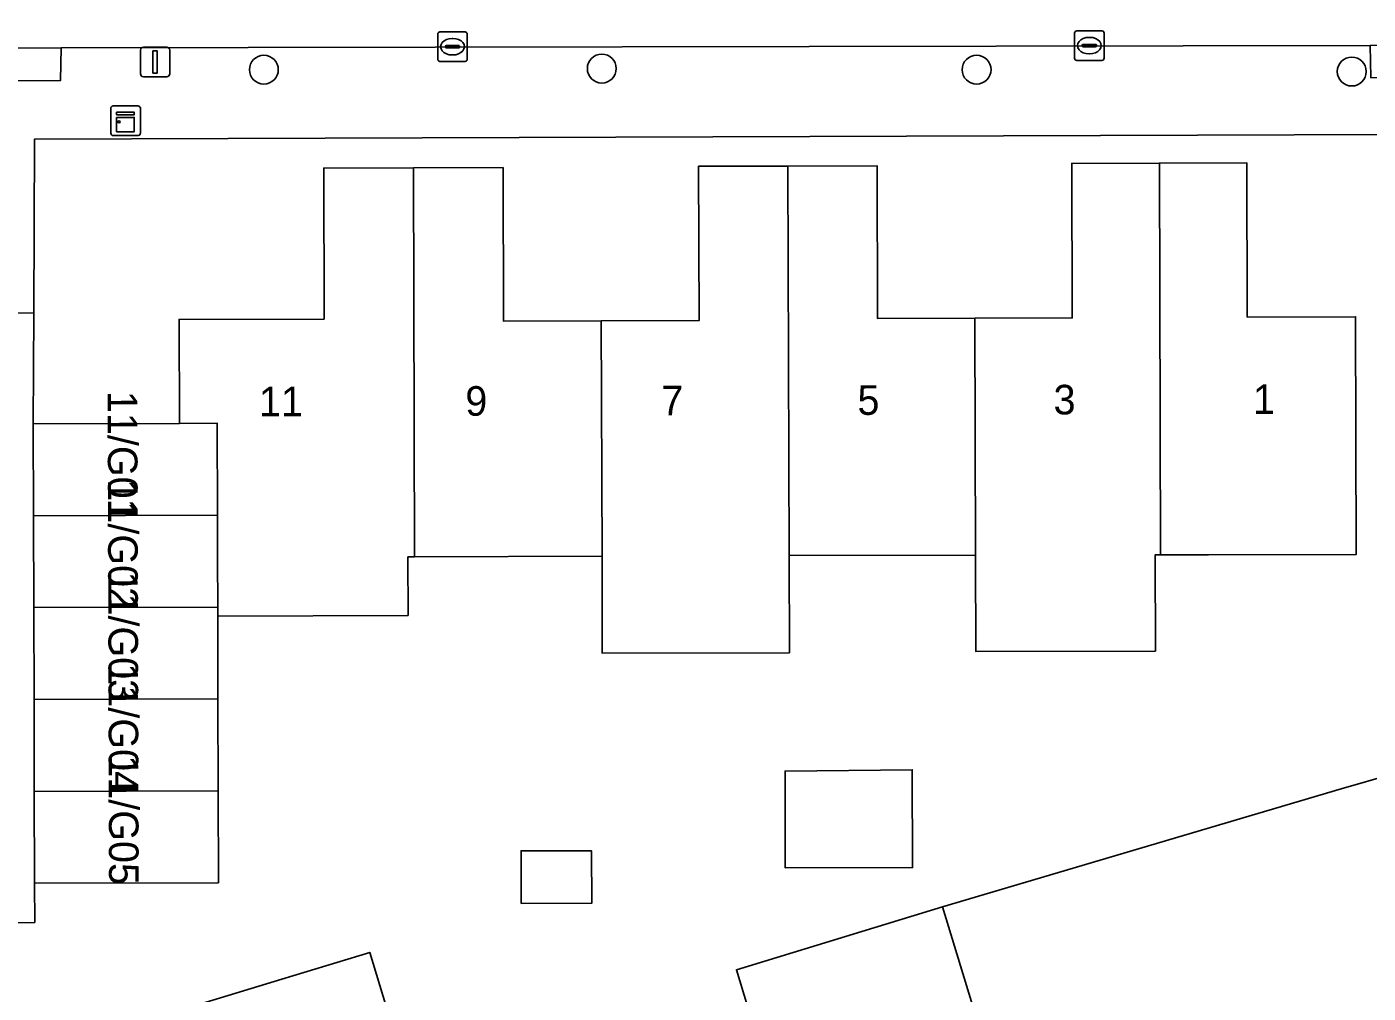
# Model space of a CAD drawing. Extents: x 160732 to 162107, y 387428 to 388479.
# Drawn here: x 161074.34 to 161119.69, y 388198.11 to 388230.78 of the extents above; entities that cross this region are included whole.
import ezdxf

# ---------------------------------------------------------------- set-up
doc = ezdxf.new("R2010")
doc.units = 0
for name, color, linetype in [('IMGEO_Boom', 7, 'Continuous'), ('IMGEO_Erf', 7, 'Continuous'), ('IMGEO_Kast', 7, 'Continuous'), ('IMGEO_Kolk', 7, 'Continuous'), ('IMGEO_Lichtmast', 7, 'Continuous'), ('IMGEO_Pand', 7, 'Continuous'), ('IMGEO_Pand_nummerreeks', 7, 'Continuous'), ('IMGEO_Parkeervlak_open', 7, 'Continuous'), ('IMGEO_Rijbaan_lokaal_open', 7, 'Continuous'), ('IMGEO_Voetpad_open', 7, 'Continuous')]:
    doc.layers.add(name, color=color, linetype=linetype)

msp = doc.modelspace()

# ---------------------------------------------------------------- linework, layer by layer
at = {"layer": 'IMGEO_Boom'}
for centre in [(161082.352, 388229.334), (161093.779, 388229.371), (161106.451, 388229.334), (161119.136, 388229.271)]:
    msp.add_circle(centre, 0.489, dxfattribs=at)
at = {"layer": 'IMGEO_Erf'}
for points in [[(161120.471, 388227.138), (161074.599, 388226.989), (161074.571, 388221.102), (161074.554, 388217.361), (161079.499, 388217.376), (161079.488, 388220.889), (161084.39, 388220.902), (161084.376, 388226.004), (161087.408, 388226.013), (161090.439, 388226.022), (161090.454, 388220.832), (161093.762, 388220.842), (161097.068, 388220.852), (161097.053, 388226.066), (161100.07, 388226.075), (161103.087, 388226.084), (161103.102, 388220.919), (161106.392, 388220.928), (161109.686, 388220.938), (161109.671, 388226.164), (161112.63, 388226.173), (161115.589, 388226.181), (161115.604, 388220.969), (161119.266, 388220.98), (161119.289, 388212.942), (161114.29, 388212.928), (161112.664, 388212.927), (161112.486, 388212.927), (161112.496, 388209.678), (161106.426, 388209.66), (161106.416, 388212.914), (161100.114, 388212.902), (161100.124, 388209.621), (161093.796, 388209.602), (161093.786, 388212.889), (161087.441, 388212.861), (161087.224, 388212.86), (161087.231, 388210.884), (161080.792, 388210.859), (161080.799, 388208.057), (161080.808, 388204.949), (161080.817, 388201.841), (161074.599, 388201.824), (161074.603, 388200.5), (161071.182, 388200.474)], [(161099.34, 388195.583), (161098.329, 388198.904), (161105.3, 388201.027), (161118.777, 388205.02), (161120.504, 388205.518)], [(161078.176, 388197.129), (161082.961, 388198.582), (161085.935, 388199.485), (161087.292, 388195.016)]]:
    msp.add_lwpolyline(points, dxfattribs=at)
for points in [[(161099.983, 388202.342), (161099.973, 388205.618), (161104.277, 388205.664), (161104.287, 388202.355)], [(161091.057, 388201.142), (161091.051, 388202.927), (161093.434, 388202.92), (161093.439, 388201.15)]]:
    msp.add_lwpolyline(points, close=True, dxfattribs=at)
at = {"layer": 'IMGEO_Kast'}
for p, q in [((161077.177, 388227.182), (161077.177, 388228.023)), ((161077.177, 388228.023), (161077.177, 388227.182)), ((161077.252, 388228.107), (161078.093, 388228.107)), ((161078.093, 388228.107), (161077.252, 388228.107)), ((161078.177, 388228.032), (161078.177, 388227.191)), ((161078.177, 388227.191), (161078.177, 388228.032)), ((161078.102, 388227.107), (161077.261, 388227.107)), ((161077.261, 388227.107), (161078.102, 388227.107))]:
    msp.add_line(p, q, dxfattribs=at)
for points in [[(161077.372, 388227.897), (161077.972, 388227.897), (161077.972, 388227.812), (161077.372, 388227.812), (161077.372, 388227.897)], [(161077.372, 388227.722), (161077.972, 388227.722), (161077.972, 388227.233), (161077.372, 388227.233), (161077.372, 388227.722)]]:
    msp.add_lwpolyline(points, dxfattribs=at)
msp.add_circle((161077.456, 388227.571), 0.0377, dxfattribs=at)
for centre, start, end in [((161077.255, 388228.029), 92.4484, 184.2845), ((161077.255, 388228.029), 92.4484, 184.2845), ((161078.099, 388228.029), 2.4484, 94.2845), ((161078.099, 388228.029), 2.4484, 94.2845), ((161077.255, 388227.185), 182.4484, 274.2845), ((161077.255, 388227.185), 182.4484, 274.2845), ((161078.099, 388227.185), 272.4484, 4.2845), ((161078.099, 388227.185), 272.4484, 4.2845)]:
    msp.add_arc(centre, 0.0779, start, end, dxfattribs=at)
at = {"layer": 'IMGEO_Kolk'}
for p, q in [((161088.23, 388229.684), (161088.23, 388230.536)), ((161088.305, 388230.61), (161089.157, 388230.61)), ((161088.718, 388230.39), (161088.743, 388230.39)), ((161089.231, 388230.536), (161089.231, 388229.684)), ((161109.763, 388229.721), (161109.763, 388230.573)), ((161109.838, 388230.647), (161110.69, 388230.647)), ((161110.251, 388230.427), (161110.276, 388230.427)), ((161110.764, 388230.573), (161110.764, 388229.721)), ((161088.489, 388230.104), (161088.489, 388230.116)), ((161088.927, 388230.067), (161088.529, 388230.067)), ((161088.532, 388230.153), (161088.93, 388230.153)), ((161088.741, 388229.83), (161088.716, 388229.83)), ((161088.973, 388230.116), (161088.973, 388230.104)), ((161110.022, 388230.141), (161110.022, 388230.153)), ((161110.46, 388230.104), (161110.062, 388230.104)), ((161110.065, 388230.19), (161110.463, 388230.19)), ((161110.274, 388229.867), (161110.249, 388229.867)), ((161110.506, 388230.153), (161110.506, 388230.141)), ((161089.157, 388229.61), (161088.305, 388229.61)), ((161110.69, 388229.647), (161109.838, 388229.647))]:
    msp.add_line(p, q, dxfattribs=at)
for points in [[(161088.23, 388229.684), (161088.23, 388230.536)], [(161088.305, 388230.61), (161089.157, 388230.61)], [(161089.231, 388230.536), (161089.231, 388229.684)], [(161109.763, 388229.721), (161109.763, 388230.573)], [(161109.838, 388230.647), (161110.69, 388230.647)], [(161110.764, 388230.573), (161110.764, 388229.721)], [(161089.157, 388229.61), (161088.305, 388229.61)], [(161110.69, 388229.647), (161109.838, 388229.647)]]:
    msp.add_lwpolyline(points, dxfattribs=at)
for centre, radius, start, end in [((161088.307, 388230.534), 0.0765, 91.552, 178.448), ((161088.307, 388230.534), 0.0765, 91.552, 178.448), ((161089.155, 388230.534), 0.0765, 1.552, 88.448), ((161089.155, 388230.534), 0.0765, 1.552, 88.448), ((161109.84, 388230.571), 0.0765, 91.552, 178.448), ((161109.84, 388230.571), 0.0765, 91.552, 178.448), ((161110.688, 388230.571), 0.0765, 1.552, 88.448), ((161110.688, 388230.571), 0.0765, 1.552, 88.448), ((161088.529, 388230.113), 0.0403, 85.8775, 175.7526), ((161088.526, 388230.103), 0.0366, 178.938, 274.7102), ((161088.93, 388230.11), 0.043, 264.8664, 352.4533), ((161088.934, 388230.115), 0.0386, 1.7309, 96.639), ((161110.062, 388230.15), 0.0403, 85.8775, 175.7526), ((161110.059, 388230.14), 0.0366, 178.938, 274.7102), ((161110.463, 388230.147), 0.043, 264.8664, 352.4533), ((161110.467, 388230.152), 0.0386, 1.7309, 96.639), ((161088.307, 388229.686), 0.0765, 181.552, 268.448), ((161088.307, 388229.686), 0.0765, 181.552, 268.448), ((161089.155, 388229.686), 0.0765, 271.552, 358.448), ((161089.155, 388229.686), 0.0765, 271.552, 358.448), ((161109.84, 388229.723), 0.0765, 181.552, 268.448), ((161109.84, 388229.723), 0.0765, 181.552, 268.448), ((161110.688, 388229.723), 0.0765, 271.552, 358.448), ((161110.688, 388229.723), 0.0765, 271.552, 358.448)]:
    msp.add_arc(centre, radius, start, end, dxfattribs=at)
for centre, major_axis, ratio, start_param, end_param in [((161088.717, 388230.11), (-0.387, 0.002), 0.722429, 4.712389, 7.853982), ((161088.742, 388230.11), (-0.39, 0.002), 0.717154, 1.570796, 4.712389), ((161110.25, 388230.147), (-0.387, 0.002), 0.722429, 4.712389, 7.853982), ((161110.275, 388230.147), (-0.39, 0.002), 0.717154, 1.570796, 4.712389)]:
    msp.add_ellipse(centre, major_axis=major_axis, ratio=ratio, start_param=start_param, end_param=end_param, dxfattribs=at)
at = {"layer": 'IMGEO_Lichtmast'}
for p, q in [((161078.179, 388229.195), (161078.179, 388229.995)), ((161078.179, 388229.995), (161078.179, 388229.195)), ((161078.279, 388230.095), (161079.069, 388230.095)), ((161079.069, 388230.095), (161078.279, 388230.095)), ((161079.169, 388229.995), (161079.169, 388229.195)), ((161079.169, 388229.195), (161079.169, 388229.995)), ((161079.069, 388229.095), (161078.279, 388229.095)), ((161078.279, 388229.095), (161079.069, 388229.095))]:
    msp.add_line(p, q, dxfattribs=at)
msp.add_lwpolyline([(161078.599, 388229.97), (161078.749, 388229.97), (161078.749, 388229.22), (161078.599, 388229.22), (161078.599, 388229.97)], dxfattribs=at)
for centre, start, end in [((161078.279, 388229.995), 90, 180), ((161078.279, 388229.995), 90, 180), ((161079.069, 388229.995), 0, 90), ((161079.069, 388229.995), 360, 90), ((161078.279, 388229.195), 180, 270), ((161078.279, 388229.195), 180, 270), ((161079.069, 388229.195), 270, 0), ((161079.069, 388229.195), 270, 0)]:
    msp.add_arc(centre, 0.1, start, end, dxfattribs=at)
at = {"layer": 'IMGEO_Pand'}
for points in [[(161087.408, 388226.013), (161084.376, 388226.004), (161084.39, 388220.902), (161079.488, 388220.889), (161079.499, 388217.376), (161080.775, 388217.38), (161080.783, 388214.272), (161080.786, 388212.831), (161080.791, 388211.164), (161080.792, 388210.859), (161087.231, 388210.884), (161087.224, 388212.86), (161087.441, 388212.861)], [(161093.762, 388220.842), (161090.454, 388220.832), (161090.439, 388226.022), (161087.408, 388226.013), (161087.441, 388212.861), (161093.786, 388212.889)], [(161100.07, 388226.075), (161097.053, 388226.066), (161097.068, 388220.852), (161093.762, 388220.842), (161093.786, 388212.889), (161093.796, 388209.602), (161100.124, 388209.621), (161100.114, 388212.902)], [(161100.114, 388212.902), (161106.416, 388212.914), (161106.392, 388220.928), (161103.102, 388220.919), (161103.087, 388226.084), (161100.07, 388226.075)], [(161112.63, 388226.173), (161109.671, 388226.164), (161109.686, 388220.938), (161106.392, 388220.928), (161106.416, 388212.914), (161106.426, 388209.66), (161112.496, 388209.678), (161112.486, 388212.927), (161112.664, 388212.927)], [(161112.664, 388212.927), (161114.29, 388212.928), (161119.289, 388212.942), (161119.266, 388220.98), (161115.604, 388220.969), (161115.589, 388226.181), (161112.63, 388226.173)], [(161074.563, 388214.254), (161080.783, 388214.272), (161080.775, 388217.38), (161079.499, 388217.376), (161074.554, 388217.361)], [(161080.786, 388212.831), (161080.783, 388214.272), (161074.563, 388214.254), (161074.572, 388211.146), (161080.791, 388211.164)], [(161080.792, 388210.859), (161080.791, 388211.164), (161074.572, 388211.146), (161074.581, 388208.039), (161080.799, 388208.057)], [(161080.799, 388208.057), (161074.581, 388208.039), (161074.59, 388204.931), (161080.808, 388204.949)], [(161099.973, 388205.618), (161099.983, 388202.342), (161104.287, 388202.355), (161104.277, 388205.664)], [(161080.808, 388204.949), (161074.59, 388204.931), (161074.599, 388201.824), (161080.817, 388201.841)], [(161091.051, 388202.927), (161091.057, 388201.142), (161093.439, 388201.15), (161093.434, 388202.92)], [(161105.3, 388201.027), (161098.329, 388198.904), (161099.34, 388195.583), (161106.311, 388197.705)], [(161089.476, 388193.715), (161088.93, 388195.513), (161087.292, 388195.016), (161085.935, 388199.485), (161082.961, 388198.582), (161078.176, 388197.129), (161078.264, 388196.841), (161077.573, 388196.631), (161078.625, 388193.166), (161079.337, 388193.383), (161080.103, 388190.86)]]:
    msp.add_lwpolyline(points, close=True, dxfattribs=at)
at = {"layer": 'IMGEO_Parkeervlak_open'}
msp.add_lwpolyline([(161074.572, 388211.146), (161074.563, 388214.254), (161074.554, 388217.361), (161074.571, 388221.102), (161068.497, 388221.153), (161068.555, 388200.454), (161071.182, 388200.474), (161074.603, 388200.5), (161074.599, 388201.824), (161074.59, 388204.931), (161074.581, 388208.039)], close=True, dxfattribs=at)
at = {"layer": 'IMGEO_Rijbaan_lokaal_open'}
for points in [[(161031.507, 388229.986), (161033.478, 388229.932), (161048.822, 388229.96), (161052.37, 388230.031), (161065.504, 388230.06), (161075.503, 388230.076), (161119.757, 388230.149), (161130.785, 388230.186), (161149.736, 388230.154), (161149.51, 388235.15)], [(161125.617, 388197.928), (161125.564, 388227.132), (161121.078, 388227.145), (161121.114, 388205.701), (161120.504, 388205.518), (161118.777, 388205.02), (161105.3, 388201.027), (161106.311, 388197.705)]]:
    msp.add_lwpolyline(points, dxfattribs=at)
at = {"layer": 'IMGEO_Voetpad_open'}
for points in [[(161150.532, 388230.153), (161149.736, 388230.154), (161130.785, 388230.186), (161130.748, 388229.063), (161119.777, 388229.065), (161119.757, 388230.149), (161075.503, 388230.076), (161075.477, 388228.97), (161064.507, 388228.939), (161064.472, 388225.06), (161053.394, 388225.023), (161053.426, 388229.075)], [(161064.507, 388228.939), (161075.477, 388228.97), (161075.503, 388230.076), (161065.504, 388230.06)], [(161047.956, 388228.994), (161047.981, 388225.033), (161034.363, 388224.965), (161034.774, 388222.134), (161039.682, 388222.115), (161039.75, 388222.857), (161043.393, 388222.874), (161043.562, 388222.888), (161049.537, 388222.899), (161049.537, 388222.765), (161052.896, 388222.739), (161057.884, 388222.701), (161057.891, 388221.129), (161062.741, 388221.118), (161068.497, 388221.153), (161074.571, 388221.102), (161074.599, 388226.989)], [(161074.599, 388226.989), (161120.471, 388227.138), (161121.078, 388227.145), (161125.564, 388227.132), (161126.663, 388227.137), (161150.612, 388227.261)]]:
    msp.add_lwpolyline(points, dxfattribs=at)

# ---------------------------------------------------------------- texts
at = {"layer": 'IMGEO_Pand_nummerreeks'}
for s, rotation, p in [('11', 0.1318, (161082.189, 388217.615)), ('9', 0.1311, (161089.165, 388217.632)), ('7', 0.1311, (161095.795, 388217.647)), ('5', 0.1311, (161102.424, 388217.662)), ('3', 0.1318, (161109.054, 388217.677)), ('1', 0.1311, (161115.798, 388217.692)), ('11/G01', 270.1659, (161077.071, 388218.472)), ('11/G02', 270.1659, (161077.079, 388215.481)), ('11/G03', 270.1659, (161077.089, 388212.368)), ('11/G04', 270.1659, (161077.097, 388209.26)), ('11/G05', 270.1659, (161077.106, 388206.153))]:
    msp.add_text(s, height=1, rotation=rotation, dxfattribs=at).set_placement(p)

doc.saveas('drawing.dxf')
